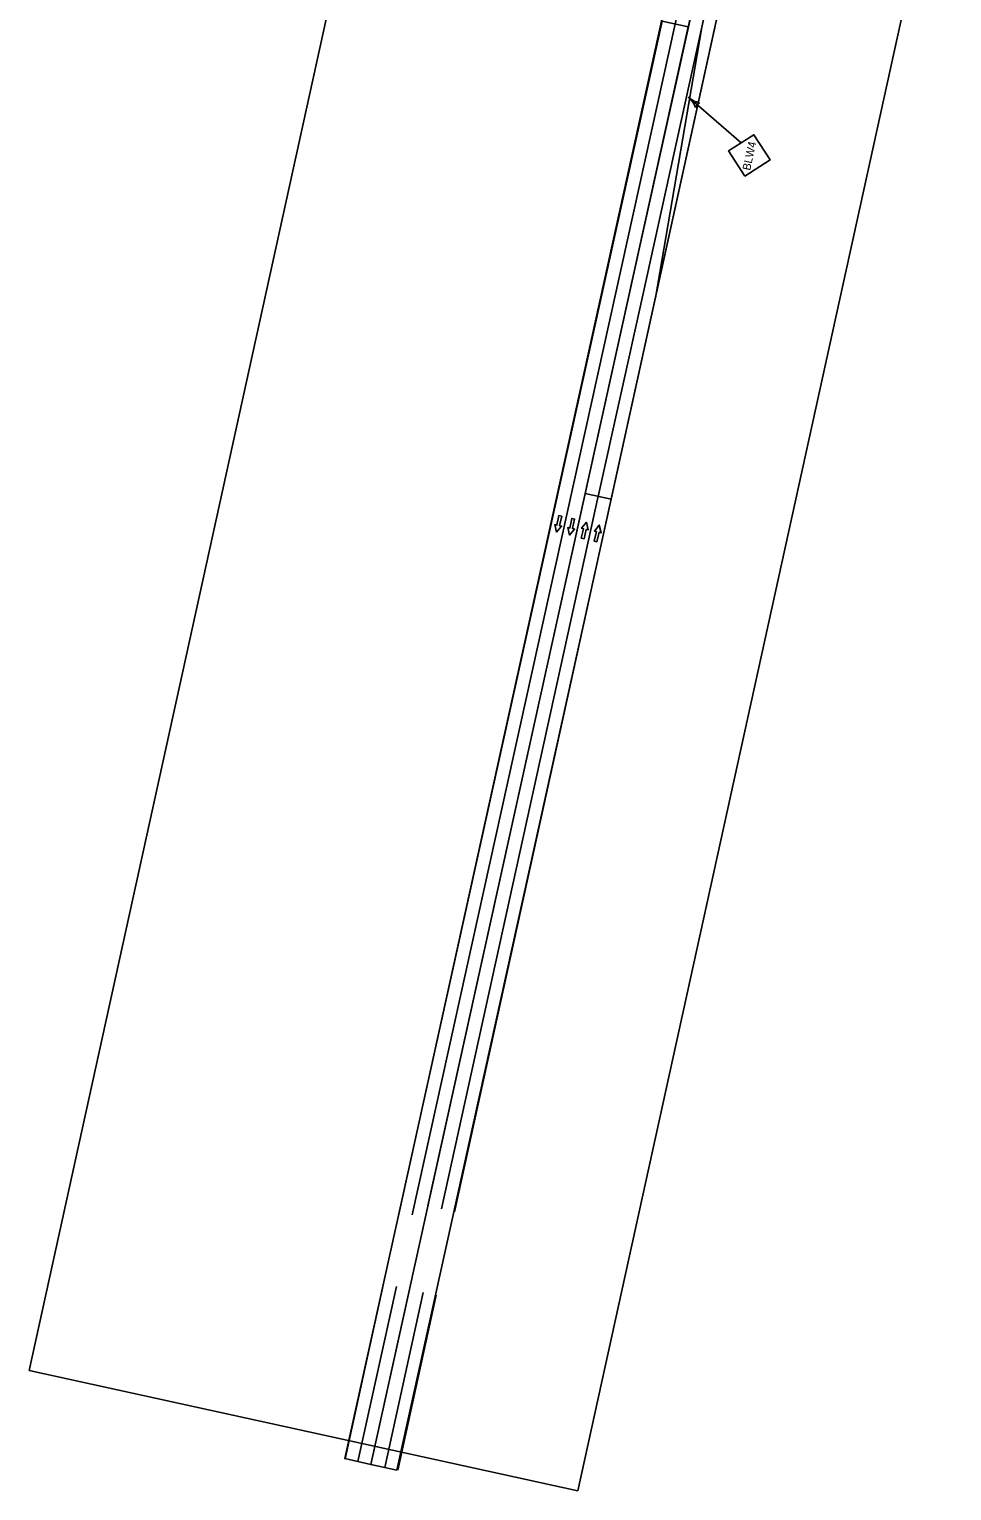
# Model space of a CAD drawing. Extents: x 14107086 to 14122011, y 8637163 to 8671583.
# Drawn here: x 14107086 to 14107915, y 8637163 to 8638478 of the extents above; entities that cross this region are included whole.
import ezdxf

# ---------------------------------------------------------------- set-up
doc = ezdxf.new("R2010")
doc.units = 0
for name, color, linetype in [('dsnNonPlotable', 7, 'Continuous'), ('dsnPaintExistingBrokenLaneLineWhite', 7, 'Continuous'), ('dsnPaintExistingDoubleCenterLineYellow', 7, 'Continuous'), ('dsnPaintExistingEdgeLineRightWhite', 7, 'Continuous'), ('dsnPaintPlaceBrokenLaneWhite', 7, 'Continuous'), ('dsnShadingPaved', 7, 'Continuous'), ('dsnStdLabel', 7, 'Continuous'), ('dsnTapeRemoveChannelizingLaneWhite', 7, 'Continuous'), ('Level 2', 7, 'Continuous'), ('Level 5', 7, 'Continuous')]:
    doc.layers.add(name, color=color, linetype=linetype)

msp = doc.modelspace()

# ---------------------------------------------------------------- linework, layer by layer
at = {"layer": 'dsnNonPlotable'}
msp.add_lwpolyline([(14107085.8, 8637271.3), (14107422.2, 8638802.3), (14107915.5, 8638693.9), (14107579.1, 8637163)], close=True, dxfattribs=at)
at = {"layer": 'dsnPaintExistingBrokenLaneLineWhite'}
for p, q in [((14107430.2, 8637411.3), (14107721.8, 8638731.5)), ((14107597.5, 8638057.5), (14107637.5, 8638238.6)), ((14107456.6, 8637416.6), (14107597.4, 8638057.6)), ((14107381.2, 8637189.3), (14107416, 8637346.7)), ((14107405.5, 8637183.9), (14107440.1, 8637341.4))]:
    msp.add_line(p, q, dxfattribs=at)
at = {"layer": 'dsnPaintExistingDoubleCenterLineYellow'}
for p, q in [((14107635.6, 8638285.4), (14107708.8, 8638616.9)), ((14107444.3, 8637419.3), (14107635.6, 8638285.4)), ((14107392.9, 8637186.7), (14107427.7, 8637344.1))]:
    msp.add_line(p, q, dxfattribs=at)
at = {"layer": 'dsnPaintExistingEdgeLineRightWhite'}
for p, q in [((14107781.7, 8639064), (14107418.2, 8637411.8)), ((14107468.3, 8637414), (14107828.5, 8639053.6)), ((14107404.4, 8637349.3), (14107369.8, 8637191.8)), ((14107417.2, 8637181.4), (14107451.8, 8637338.8))]:
    msp.add_line(p, q, dxfattribs=at)
at = {"layer": 'dsnPaintPlaceBrokenLaneWhite'}
msp.add_line((14107637.5, 8638238.6), (14107756.2, 8638776), dxfattribs=at)
at = {"layer": 'dsnShadingPaved'}
for points in [[(14107831.9, 8639180.9), (14107855.4, 8639175.8), (14107609.2, 8638054.9), (14107585.8, 8638060.2), (14107635.6, 8638285.4), (14107744.5, 8638778.6), (14107806.3, 8639058.6), (14107805.1, 8639058.9)], [(14107392.9, 8637186.7), (14107369.5, 8637191.9), (14107655.1, 8638485.1), (14107678.5, 8638480)], [(14107416.4, 8637181.6), (14107609.2, 8638054.9), (14107585.8, 8638060.1), (14107392.9, 8637186.7)]]:
    msp.add_lwpolyline(points, close=True, dxfattribs=at)
at = {"layer": 'dsnStdLabel'}
msp.add_line((14107726.2, 8638375.6), (14107678.6, 8638416.6), dxfattribs=at)
msp.add_lwpolyline([(14107729.4, 8638345.6), (14107752.1, 8638360.2), (14107737.6, 8638382.9), (14107714.8, 8638368.4)], close=True, dxfattribs=at)
for centre, radius, start, end in [((14107663.6, 8638399.2), 22.9, 21.2592, 49.3305), ((14107693.5, 8638434), 22.9, 229.3304, 257.4016), ((14107693.1, 8638404), 8.86, 121.5962, 157.0647)]:
    msp.add_arc(centre, radius, start, end, dxfattribs=at)
at = {"layer": 'dsnTapeRemoveChannelizingLaneWhite'}
msp.add_line((14107690.3, 8638477.8), (14107649, 8638236.1), dxfattribs=at)
at = {"layer": 'Level 2'}
for points in [[(14107564.7, 8638039.7), (14107562.2, 8638040.3), (14107560.3, 8638031.8), (14107558.4, 8638032.2), (14107560.1, 8638025.4), (14107564.5, 8638030.8), (14107562.7, 8638031.2)], [(14107576.3, 8638037.1), (14107573.8, 8638037.7), (14107571.9, 8638029.1), (14107570.1, 8638029.5), (14107571.7, 8638022.8), (14107576.2, 8638028.1), (14107574.3, 8638028.6)], [(14107582.3, 8638020), (14107584.8, 8638019.4), (14107586.7, 8638027.9), (14107588.6, 8638027.5), (14107586.9, 8638034.3), (14107582.5, 8638028.9), (14107584.3, 8638028.5)], [(14107594, 8638017.3), (14107596.4, 8638016.8), (14107598.4, 8638025.3), (14107600.2, 8638024.9), (14107598.5, 8638031.7), (14107594.1, 8638026.3), (14107595.9, 8638025.9)]]:
    msp.add_lwpolyline(points, close=True, dxfattribs=at)
at = {"layer": 'Level 5'}
for points in [[(14107562.7, 8638031.2), (14107564.5, 8638030.8), (14107560.1, 8638025.4), (14107558.4, 8638032.2), (14107560.3, 8638031.8), (14107562.2, 8638040.3), (14107564.7, 8638039.7), (14107562.7, 8638031.2)], [(14107574.3, 8638028.6), (14107576.2, 8638028.1), (14107571.7, 8638022.8), (14107570.1, 8638029.5), (14107571.9, 8638029.1), (14107573.8, 8638037.7), (14107576.3, 8638037.1), (14107574.3, 8638028.6)], [(14107584.3, 8638028.5), (14107582.5, 8638028.9), (14107586.9, 8638034.3), (14107588.6, 8638027.5), (14107586.7, 8638027.9), (14107584.8, 8638019.4), (14107582.3, 8638020), (14107584.3, 8638028.5)], [(14107595.9, 8638025.9), (14107594.1, 8638026.3), (14107598.5, 8638031.7), (14107600.2, 8638024.9), (14107598.4, 8638025.3), (14107596.4, 8638016.8), (14107594, 8638017.3), (14107595.9, 8638025.9)]]:
    msp.add_lwpolyline(points, dxfattribs=at)

# ---------------------------------------------------------------- texts
at = {"layer": 'dsnStdLabel'}
msp.add_text('BLW4', height=7.2, rotation=77.6078, dxfattribs=at).set_placement((14107734.1, 8638350.3))

doc.saveas('drawing.dxf')
